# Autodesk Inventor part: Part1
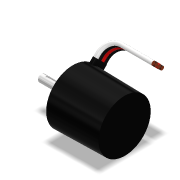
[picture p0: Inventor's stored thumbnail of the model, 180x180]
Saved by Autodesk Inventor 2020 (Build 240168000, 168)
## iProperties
Created: 2020-11
Part Number: Part1
Material: Generic
Document SubType Name: Modeling
Designer: Greg
Density: 1 g/cm^3
Appearance: Default
Author: Greg
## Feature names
1. Revolution1
2. Fillet1
3. Hole1
4. Extrusion1
5. Extrusion2
6. Sweep1
## Parameters: d1 = 58.166 mm, d2 = 9.525 mm, d3 = 3.556 mm, d4 = 31.496 mm, d5 = 29.972 mm, d7 = 89 deg, d8 = 90 deg, d9 = 0.508 mm, d11 = 50.8 mm, d12 = 3.9624 mm, d13 = 5.08 mm, d14 = 9.525 mm, d15 = 6.35 mm, d16 = 82 deg, d17 = 7.62 mm, d18 = 118 deg, d19 = 2.0066 mm, d20 = 21.9964 mm, d21 = 6.096 mm, d22 = 1.016 mm, d23 = 0, d24 = 45 deg, d25 = 2.54 mm, d26 = 13.462 mm, d27 = 5.08 mm, d28 = 5.08 mm, d29 = 0, d30 = 5.08 mm, d31 = 0, d32 = 4.572 mm, d33 = 4.064 mm, d34 = 4.572 mm, d35 = 4.572 mm, d36 = 4.572 mm, d39 = 19.05 mm, d40 = 50.8 mm, d41 = 15.24 mm, d42 = 0, d43 = 0, d44 = 4.0005 mm
